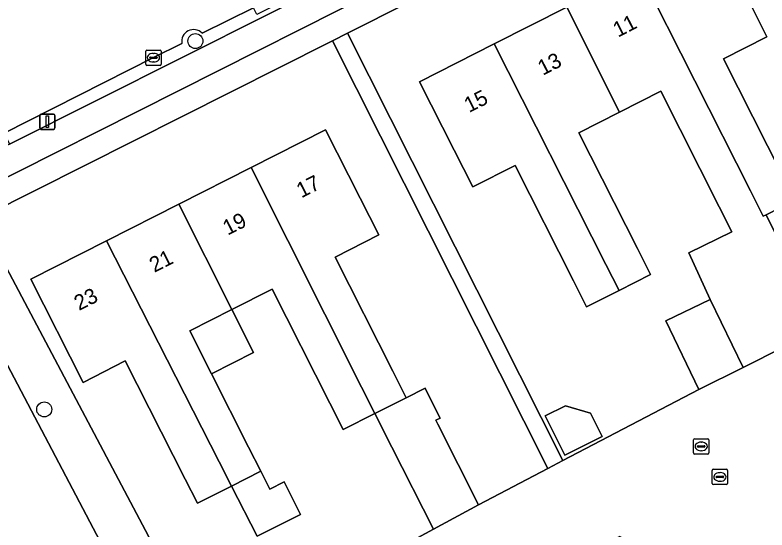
# Model space of a CAD drawing. Extents: x 157320 to 158835, y 386650 to 388491.
# Drawn here: x 157689.7 to 157738.7, y 387668.55 to 387702.1 of the extents above; entities that cross this region are included whole.
import ezdxf

# ---------------------------------------------------------------- set-up
doc = ezdxf.new("R2010")
doc.units = 0
for name, color, linetype in [('IMGEO_Berm_open', 7, 'Continuous'), ('IMGEO_Boom', 7, 'Continuous'), ('IMGEO_Erf', 7, 'Continuous'), ('IMGEO_Fietspad_open', 7, 'Continuous'), ('IMGEO_Kolk', 7, 'Continuous'), ('IMGEO_Lichtmast', 7, 'Continuous'), ('IMGEO_Pand', 7, 'Continuous'), ('IMGEO_Pand_nummerreeks', 7, 'Continuous'), ('IMGEO_Rijbaan_lokaal_open', 7, 'Continuous'), ('IMGEO_Rioolput', 7, 'Continuous'), ('IMGEO_Voetpad_open', 7, 'Continuous')]:
    doc.layers.add(name, color=color, linetype=linetype)

msp = doc.modelspace()

# ---------------------------------------------------------------- linework, layer by layer
at = {"layer": 'IMGEO_Berm_open'}
for points in [[(157700.572, 387700.24), (157698.721, 387699.326), (157688.986, 387694.407), (157689.342, 387693.698), (157711.843, 387704.997), (157740.534, 387719.377)], [(157721.203, 387710.609), (157719.432, 387709.714), (157712.036, 387706.007), (157712.245, 387705.562), (157705.464, 387702.145), (157705.231, 387702.581), (157701.888, 387700.919)]]:
    msp.add_lwpolyline(points, dxfattribs=at)
msp.add_arc((157701.333, 387700.381), 0.774, 44.1134, 190.4702, dxfattribs=at)
at = {"layer": 'IMGEO_Boom'}
for centre in [(157701.451, 387700.406), (157691.602, 387676.406)]:
    msp.add_circle(centre, 0.489, dxfattribs=at)
at = {"layer": 'IMGEO_Erf'}
for points in [[(157738.665, 387714.671), (157711.366, 387700.916), (157725.398, 387673.067), (157734.251, 387677.701), (157732.112, 387682.182), (157735.005, 387683.563), (157733.618, 387686.613), (157736.414, 387687.974), (157735.586, 387689.61), (157731.776, 387697.137), (157729.091, 387695.778), (157726.434, 387694.433), (157730.254, 387686.888), (157731.108, 387685.201), (157729.061, 387684.165), (157726.947, 387683.095), (157726.093, 387684.781), (157722.29, 387692.292), (157719.536, 387690.898), (157718.321, 387693.298), (157716.063, 387697.759), (157720.927, 387700.221), (157725.654, 387702.615)], [(157737.518, 387703.018), (157738.702, 387700.68), (157735.857, 387699.24), (157739.682, 387691.684), (157740.515, 387690.039), (157738.641, 387689.09), (157741.294, 387683.711), (157744.821, 387693.675), (157768.381, 387699.017)], [(157688.751, 387686.376), (157702.357, 387660.686), (157716.966, 387668.61), (157714.244, 387673.947), (157713.149, 387676.133), (157711.089, 387675.092), (157710.214, 387676.823), (157706.465, 387684.243), (157703.823, 387682.908), (157705.23, 387680.109), (157702.502, 387678.73), (157704.914, 387673.957), (157705.714, 387672.375), (157706.299, 387671.216), (157707.229, 387671.686), (157708.301, 387669.565), (157705.482, 387668.141), (157703.811, 387671.413), (157701.584, 387670.288), (157700.785, 387671.865), (157696.885, 387679.564), (157694.132, 387678.17), (157690.723, 387684.899), (157695.651, 387687.395), (157700.367, 387689.783), (157705.082, 387692.172), (157709.938, 387694.631), (157712.193, 387690.168), (157713.404, 387687.772), (157710.553, 387686.332), (157714.311, 387678.894), (157715.186, 387677.163), (157716.419, 387677.786), (157716.6, 387677.425), (157717.399, 387675.835), (157717.124, 387675.696), (157717.249, 387675.453), (157719.895, 387670.186), (157724.43, 387672.56), (157710.377, 387700.417), (157710.131, 387700.293), (157687.838, 387689.089)]]:
    msp.add_lwpolyline(points, dxfattribs=at)
msp.add_lwpolyline([(157725.535, 387673.42), (157724.256, 387675.981), (157725.564, 387676.634), (157727.205, 387676.169), (157727.97, 387674.636)], close=True, dxfattribs=at)
at = {"layer": 'IMGEO_Fietspad_open'}
msp.add_lwpolyline([(157759.18, 387728.971), (157759.256, 387728.788), (157740.534, 387719.377), (157711.843, 387704.997), (157689.342, 387693.698), (157686.319, 387692.175), (157687.224, 387690.567), (157713.444, 387703.783), (157738.499, 387716.361), (157762.207, 387728.221)], dxfattribs=at)
at = {"layer": 'IMGEO_Kolk'}
for p, q in [((157698.295, 387699.824), (157699.147, 387699.824)), ((157698.22, 387698.898), (157698.22, 387699.75)), ((157698.479, 387699.318), (157698.479, 387699.33)), ((157698.917, 387699.281), (157698.519, 387699.281)), ((157698.522, 387699.367), (157698.92, 387699.367)), ((157698.708, 387699.604), (157698.733, 387699.604)), ((157698.963, 387699.33), (157698.963, 387699.318)), ((157699.221, 387699.75), (157699.221, 387698.898)), ((157699.147, 387698.824), (157698.295, 387698.824)), ((157698.731, 387699.044), (157698.706, 387699.044)), ((157735.135, 387671.579), (157735.135, 387672.431)), ((157735.21, 387672.505), (157736.062, 387672.505)), ((157736.136, 387672.431), (157736.136, 387671.579)), ((157735.394, 387671.999), (157735.394, 387672.011)), ((157735.832, 387671.962), (157735.434, 387671.962)), ((157735.437, 387672.048), (157735.835, 387672.048)), ((157735.623, 387672.285), (157735.648, 387672.285)), ((157735.878, 387672.011), (157735.878, 387671.999)), ((157736.062, 387671.505), (157735.21, 387671.505)), ((157735.646, 387671.725), (157735.621, 387671.725))]:
    msp.add_line(p, q, dxfattribs=at)
for points in [[(157698.295, 387699.824), (157699.147, 387699.824)], [(157698.22, 387698.898), (157698.22, 387699.75)], [(157699.221, 387699.75), (157699.221, 387698.898)], [(157699.147, 387698.824), (157698.295, 387698.824)], [(157735.135, 387671.579), (157735.135, 387672.431)], [(157735.21, 387672.505), (157736.062, 387672.505)], [(157736.136, 387672.431), (157736.136, 387671.579)], [(157736.062, 387671.505), (157735.21, 387671.505)]]:
    msp.add_lwpolyline(points, dxfattribs=at)
for centre, radius, start, end in [((157698.297, 387699.748), 0.0765, 91.552, 178.448), ((157698.297, 387699.748), 0.0765, 91.552, 178.448), ((157699.145, 387699.748), 0.0765, 1.552, 88.448), ((157699.145, 387699.748), 0.0765, 1.552, 88.448), ((157698.519, 387699.327), 0.0403, 85.8775, 175.7526), ((157698.516, 387699.317), 0.0366, 178.938, 274.7102), ((157698.92, 387699.324), 0.043, 264.8664, 352.4533), ((157698.924, 387699.329), 0.0386, 1.7309, 96.639), ((157698.297, 387698.9), 0.0765, 181.552, 268.448), ((157698.297, 387698.9), 0.0765, 181.552, 268.448), ((157699.145, 387698.9), 0.0765, 271.552, 358.448), ((157699.145, 387698.9), 0.0765, 271.552, 358.448), ((157735.212, 387672.429), 0.0765, 91.552, 178.448), ((157735.212, 387672.429), 0.0765, 91.552, 178.448), ((157736.06, 387672.429), 0.0765, 1.552, 88.448), ((157736.06, 387672.429), 0.0765, 1.552, 88.448), ((157735.434, 387672.008), 0.0403, 85.8775, 175.7526), ((157735.431, 387671.998), 0.0366, 178.938, 274.7102), ((157735.835, 387672.005), 0.043, 264.8664, 352.4533), ((157735.839, 387672.01), 0.0386, 1.7309, 96.639), ((157735.212, 387671.581), 0.0765, 181.552, 268.448), ((157735.212, 387671.581), 0.0765, 181.552, 268.448), ((157736.06, 387671.581), 0.0765, 271.552, 358.448), ((157736.06, 387671.581), 0.0765, 271.552, 358.448)]:
    msp.add_arc(centre, radius, start, end, dxfattribs=at)
for centre, major_axis, ratio, start_param, end_param in [((157698.707, 387699.324), (-0.387, 0.002), 0.722429, 4.712389, 7.853982), ((157698.732, 387699.324), (-0.39, 0.002), 0.717154, 1.570796, 4.712389), ((157735.622, 387672.005), (-0.387, 0.002), 0.722429, 4.712389, 7.853982), ((157735.647, 387672.005), (-0.39, 0.002), 0.717154, 1.570796, 4.712389)]:
    msp.add_ellipse(centre, major_axis=major_axis, ratio=ratio, start_param=start_param, end_param=end_param, dxfattribs=at)
at = {"layer": 'IMGEO_Lichtmast'}
for p, q in [((157691.311, 387694.752), (157691.311, 387695.552)), ((157691.311, 387695.552), (157691.311, 387694.752)), ((157691.411, 387695.652), (157692.201, 387695.652)), ((157692.201, 387695.652), (157691.411, 387695.652)), ((157692.301, 387695.552), (157692.301, 387694.752)), ((157692.301, 387694.752), (157692.301, 387695.552)), ((157692.201, 387694.652), (157691.411, 387694.652)), ((157691.411, 387694.652), (157692.201, 387694.652))]:
    msp.add_line(p, q, dxfattribs=at)
msp.add_lwpolyline([(157691.731, 387695.527), (157691.881, 387695.527), (157691.881, 387694.777), (157691.731, 387694.777), (157691.731, 387695.527)], dxfattribs=at)
for centre, start, end in [((157691.411, 387695.552), 90, 180), ((157691.411, 387695.552), 90, 180), ((157692.201, 387695.552), 0, 90), ((157692.201, 387695.552), 360, 90), ((157691.411, 387694.752), 180, 270), ((157691.411, 387694.752), 180, 270), ((157692.201, 387694.752), 270, 0), ((157692.201, 387694.752), 270, 0)]:
    msp.add_arc(centre, 0.1, start, end, dxfattribs=at)
at = {"layer": 'IMGEO_Pand'}
for points in [[(157735.857, 387699.24), (157738.702, 387700.68), (157737.518, 387703.018), (157735.26, 387707.478), (157730.381, 387705.008), (157737.623, 387690.641), (157738.453, 387688.995), (157738.641, 387689.09), (157740.515, 387690.039), (157739.682, 387691.684)], [(157729.091, 387695.778), (157731.776, 387697.137), (157735.586, 387689.61), (157736.414, 387687.974), (157733.618, 387686.613), (157735.005, 387683.563), (157737.144, 387679.146), (157739.786, 387680.465), (157741.294, 387683.711), (157738.641, 387689.09), (157738.453, 387688.995), (157737.623, 387690.641), (157730.381, 387705.008), (157725.654, 387702.615)], [(157725.654, 387702.615), (157720.927, 387700.221), (157728.207, 387685.851), (157729.061, 387684.165), (157731.108, 387685.201), (157730.254, 387686.888), (157726.434, 387694.433), (157729.091, 387695.778)], [(157720.927, 387700.221), (157716.063, 387697.759), (157718.321, 387693.298), (157719.536, 387690.898), (157722.29, 387692.292), (157726.093, 387684.781), (157726.947, 387683.095), (157729.061, 387684.165), (157728.207, 387685.851)], [(157712.193, 387690.168), (157709.938, 387694.631), (157705.082, 387692.172), (157712.277, 387677.866), (157713.149, 387676.133), (157715.186, 387677.163), (157714.311, 387678.894), (157710.553, 387686.332), (157713.404, 387687.772)], [(157705.082, 387692.172), (157700.367, 387689.783), (157703.823, 387682.908), (157706.465, 387684.243), (157710.214, 387676.823), (157711.089, 387675.092), (157713.149, 387676.133), (157712.277, 387677.866)], [(157700.367, 387689.783), (157695.651, 387687.395), (157703.006, 387672.99), (157703.811, 387671.413), (157705.714, 387672.375), (157704.914, 387673.957), (157702.502, 387678.73), (157701.089, 387681.526), (157703.823, 387682.908)], [(157695.651, 387687.395), (157690.723, 387684.899), (157694.132, 387678.17), (157696.885, 387679.564), (157700.785, 387671.865), (157701.584, 387670.288), (157703.811, 387671.413), (157703.006, 387672.99)], [(157735.005, 387683.563), (157732.112, 387682.182), (157734.251, 387677.701), (157737.144, 387679.146)], [(157703.823, 387682.908), (157701.089, 387681.526), (157702.502, 387678.73), (157705.23, 387680.109)], [(157717.249, 387675.453), (157717.124, 387675.696), (157717.399, 387675.835), (157716.6, 387677.425), (157716.419, 387677.786), (157715.186, 387677.163), (157713.149, 387676.133), (157714.244, 387673.947), (157716.966, 387668.61), (157719.895, 387670.186)], [(157725.535, 387673.42), (157727.97, 387674.636), (157727.205, 387676.169), (157725.564, 387676.634), (157724.256, 387675.981)], [(157705.714, 387672.375), (157703.811, 387671.413), (157705.482, 387668.141), (157708.301, 387669.565), (157707.229, 387671.686), (157706.299, 387671.216)]]:
    msp.add_lwpolyline(points, close=True, dxfattribs=at)
at = {"layer": 'IMGEO_Rijbaan_lokaal_open'}
for points in [[(157701.888, 387700.919), (157705.231, 387702.581), (157712.036, 387706.007), (157719.432, 387709.714), (157721.203, 387710.609)], [(157667.432, 387683.529), (157671.065, 387685.405), (157672.08, 387685.911), (157688.986, 387694.407), (157698.721, 387699.326), (157700.572, 387700.24)], [(157713.019, 387634.314), (157706.841, 387645.947), (157703.178, 387652.824), (157699.49, 387659.747), (157688.746, 387680.168), (157687.095, 387683.297), (157681.78, 387680.52), (157682.969, 387678.312), (157691.238, 387662.698), (157694.131, 387657.241), (157696.634, 387652.576), (157698.396, 387649.256), (157698.977, 387648.175), (157702.955, 387640.64), (157704.707, 387637.298), (157708.819, 387629.59)], [(157739.786, 387680.465), (157737.144, 387679.146), (157734.251, 387677.701), (157725.398, 387673.067), (157724.43, 387672.56), (157719.895, 387670.186), (157716.966, 387668.61), (157702.357, 387660.686), (157705.154, 387655.407), (157714.08, 387660.15), (157718.497, 387662.495), (157721.296, 387663.982), (157729.131, 387668.147), (157731.508, 387663.438), (157732.922, 387660.638), (157734.375, 387657.76), (157737.162, 387652.744), (157738.521, 387649.989), (157740.009, 387646.975)]]:
    msp.add_lwpolyline(points, dxfattribs=at)
msp.add_arc((157701.333, 387700.381), 0.774, 44.1134, 190.4702, dxfattribs=at)
at = {"layer": 'IMGEO_Rioolput'}
for p, q in [((157733.914, 387673.57), (157733.914, 387674.422)), ((157733.989, 387674.496), (157734.841, 387674.496)), ((157734.915, 387674.422), (157734.915, 387673.57)), ((157734.173, 387673.99), (157734.173, 387674.002)), ((157734.611, 387673.953), (157734.213, 387673.953)), ((157734.216, 387674.039), (157734.614, 387674.039)), ((157734.402, 387674.276), (157734.427, 387674.276)), ((157734.657, 387674.002), (157734.657, 387673.99)), ((157734.841, 387673.496), (157733.989, 387673.496)), ((157734.425, 387673.716), (157734.4, 387673.716))]:
    msp.add_line(p, q, dxfattribs=at)
for points in [[(157733.914, 387673.57), (157733.914, 387674.422)], [(157733.989, 387674.496), (157734.841, 387674.496)], [(157734.915, 387674.422), (157734.915, 387673.57)], [(157734.841, 387673.496), (157733.989, 387673.496)]]:
    msp.add_lwpolyline(points, dxfattribs=at)
for centre, radius, start, end in [((157733.991, 387674.42), 0.0765, 91.552, 178.448), ((157733.991, 387674.42), 0.0765, 91.552, 178.448), ((157734.839, 387674.42), 0.0765, 1.552, 88.448), ((157734.839, 387674.42), 0.0765, 1.552, 88.448), ((157734.213, 387673.999), 0.0403, 85.8775, 175.7526), ((157734.21, 387673.989), 0.0366, 178.938, 274.7102), ((157734.614, 387673.996), 0.043, 264.8664, 352.4533), ((157734.618, 387674.001), 0.0386, 1.7309, 96.639), ((157733.991, 387673.572), 0.0765, 181.552, 268.448), ((157733.991, 387673.572), 0.0765, 181.552, 268.448), ((157734.839, 387673.572), 0.0765, 271.552, 358.448), ((157734.839, 387673.572), 0.0765, 271.552, 358.448)]:
    msp.add_arc(centre, radius, start, end, dxfattribs=at)
for centre, major_axis, ratio, start_param, end_param in [((157734.401, 387673.996), (-0.387, 0.002), 0.722429, 4.712389, 7.853982), ((157734.426, 387673.996), (-0.39, 0.002), 0.717154, 1.570796, 4.712389)]:
    msp.add_ellipse(centre, major_axis=major_axis, ratio=ratio, start_param=start_param, end_param=end_param, dxfattribs=at)
at = {"layer": 'IMGEO_Voetpad_open'}
for points in [[(157762.207, 387728.221), (157738.499, 387716.361), (157713.444, 387703.783), (157687.224, 387690.567)], [(157685.683, 387687.979), (157687.838, 387689.089), (157710.131, 387700.293), (157710.377, 387700.417), (157711.356, 387700.911), (157711.366, 387700.916), (157738.665, 387714.671), (157751.329, 387720.948), (157763.477, 387727.084)], [(157705.212, 387655.297), (157705.154, 387655.407), (157702.357, 387660.686), (157688.751, 387686.376), (157687.763, 387688.247), (157687.838, 387689.089), (157685.683, 387687.979)], [(157686.238, 387685.019), (157687.095, 387683.297), (157688.746, 387680.168), (157699.49, 387659.747), (157700.408, 387660.236), (157704.096, 387653.313), (157703.178, 387652.824), (157706.841, 387645.947), (157713.019, 387634.314), (157729.998, 387602.392), (157735.466, 387592.089), (157735.907, 387592.323), (157740.185, 387584.261), (157739.744, 387584.027), (157740.957, 387581.742)]]:
    msp.add_lwpolyline(points, dxfattribs=at)
msp.add_lwpolyline([(157711.366, 387700.916), (157711.356, 387700.911), (157710.377, 387700.417), (157724.43, 387672.56), (157725.398, 387673.067)], close=True, dxfattribs=at)

# ---------------------------------------------------------------- texts
at = {"layer": 'IMGEO_Pand_nummerreeks'}
for s, rotation, p in [('11', 26.852, (157728.988, 387700.626)), ('13', 26.8545, (157724.087, 387698.145)), ('15', 26.8545, (157719.288, 387695.716)), ('17', 26.8603, (157708.361, 387690.155)), ('19', 26.8603, (157703.558, 387687.722)), ('21', 26.8603, (157698.774, 387685.299)), ('23', 26.8603, (157693.869, 387682.815))]:
    msp.add_text(s, height=1, rotation=rotation, dxfattribs=at).set_placement(p)

doc.saveas('drawing.dxf')
